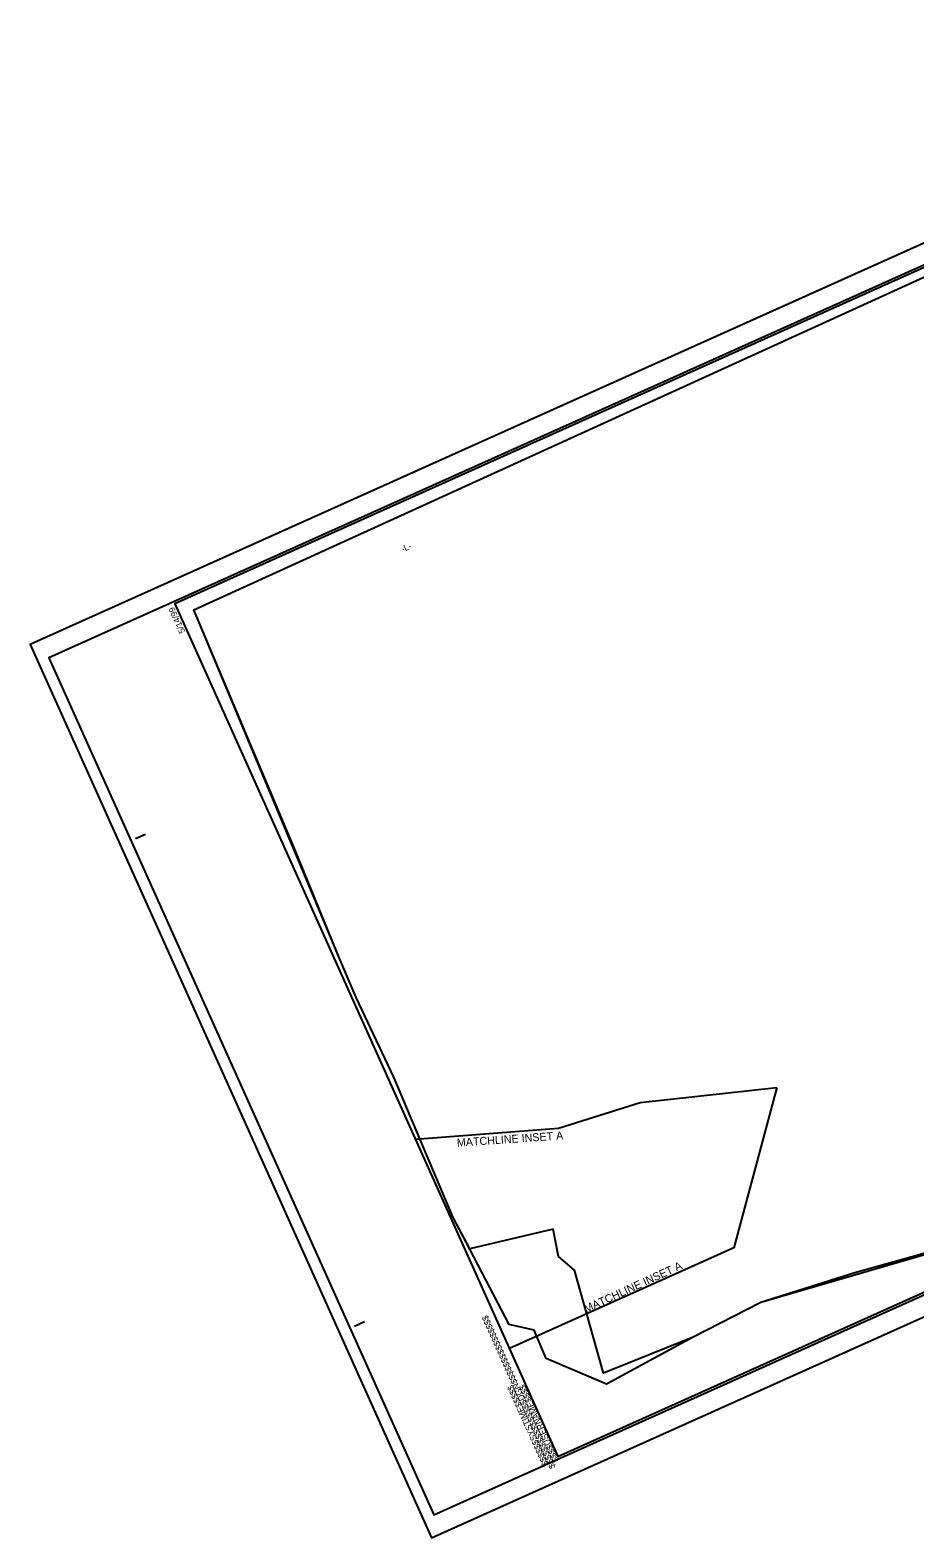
# Model space of a CAD drawing. Extents: x 553939 to 555925, y 502653 to 504347.
# Drawn here: x 553939 to 554932, y 502653 to 504347 of the extents above; entities that cross this region are included whole.
import ezdxf

# ---------------------------------------------------------------- set-up
doc = ezdxf.new("R2010")
doc.units = 0
for name, color, linetype in [('Matchline', 7, 'Continuous'), ('Matchline Text', 7, 'Continuous'), ('Prop Horizontal Alignment Station Label', 7, 'Continuous'), ('Sheet Border Standard 30in CELL', 7, 'Continuous'), ('Sheet Clip Boundary CELL', 7, 'Continuous'), ('Sheet Cutting Line CELL', 7, 'Continuous'), ('Sheet Plot Border Inside CELL', 7, 'Continuous'), ('Sheet Plot Border Outside CELL', 7, 'Continuous')]:
    doc.layers.add(name, color=color, linetype=linetype)

msp = doc.modelspace()

# ---------------------------------------------------------------- linework, layer by layer
at = {"layer": 'Matchline'}
for p, q in [((554623.6, 503142.1), (554777.2, 503159.2)), ((554777.2, 503159.2), (554728.8, 502978.9)), ((554532, 503113.5), (554623.6, 503142.1)), ((554371.3, 503101), (554532, 503113.5)), ((554728.8, 502978.9), (554476.9, 502865.8))]:
    msp.add_line(p, q, dxfattribs=at)
at = {"layer": 'Sheet Border Standard 30in CELL'}
for p, q in [((554102.1, 503702.8), (554102.1, 503702.8)), ((554056.9, 503438.6), (554068.3, 503443.7)), ((554302.7, 502891.2), (554314.1, 502896.4))]:
    msp.add_line(p, q, dxfattribs=at)
msp.add_lwpolyline([(555469.6, 504316.8), (554101.2, 503702.4), (554531.3, 502744.5), (555899.7, 503359)], close=True, dxfattribs=at)
at = {"layer": 'Sheet Clip Boundary CELL'}
for points in [[(555094.7, 503015.3), (554759.3, 502917.8), (554683, 502878.6), (554586, 502826.1), (554517.9, 502854.7), (554504.5, 502886.7), (554476.7, 502893.1), (554428.4, 502985.5), (554413.3, 503013.9), (554346.9, 503170.6), (554304.9, 503260.3), (554285.2, 503305.8), (554122.4, 503695.7), (555128.4, 504154.2)], [(555094.7, 503015.3), (554864.6, 502951), (554759.3, 502917.8), (554683, 502878.6), (554582.3, 502838.3), (554549.8, 502954), (554532.1, 502969.2), (554526, 503000), (554432.2, 502977.8), (554413.3, 503013.9), (554346.9, 503170.6), (554304.9, 503260.3), (554285.2, 503305.8), (554236.8, 503423.9), (554122.4, 503695.7), (555128.4, 504154.2)]]:
    msp.add_lwpolyline(points, dxfattribs=at)
at = {"layer": 'Sheet Cutting Line CELL'}
for p, q in [((555474.9, 504346.6), (553938.6, 503656.8)), ((553938.6, 503656.8), (554389.2, 502653.3)), ((554389.2, 502653.3), (555925.5, 503343.1))]:
    msp.add_line(p, q, dxfattribs=at)
at = {"layer": 'Sheet Plot Border Inside CELL'}
msp.add_lwpolyline([(555480, 504324.3), (553959.7, 503641.6), (554391.9, 502679.1), (555912.2, 503361.8)], close=True, dxfattribs=at)
at = {"layer": 'Sheet Plot Border Outside CELL'}
msp.add_lwpolyline([(555474.9, 504346.6), (553938.6, 503656.8), (554389.2, 502653.3), (555925.5, 503343.1)], close=True, dxfattribs=at)

# ---------------------------------------------------------------- texts
at = {"layer": 'Matchline Text'}
for rotation, p in [(3.9694, (554418.1, 503092.6)), (24.7503, (554563.1, 502905.8))]:
    msp.add_text('MATCHLINE INSET A', height=9, rotation=rotation, dxfattribs=at).set_placement(p)
at = {"layer": 'Prop Horizontal Alignment Station Label'}
msp.add_text('-L-', height=7, rotation=24.1816, dxfattribs=at).set_placement((554357.1, 503760.1))
at = {"layer": 'Sheet Border Standard 30in CELL'}
for s, p in [('5/14/99', (554112.9, 503671)), ('$$$$$$$$$$$$$$$$DGN$$$$$$$$$$$$$$$$', (554528.7, 502732.9)), ('$$$$$$SYSTIME$$$$$', (554520.8, 502735.7)), ('$$$$USERNAME$$$$', (554532.5, 502739.9))]:
    msp.add_text(s, height=7, rotation=114.1816, dxfattribs=at).set_placement(p)

doc.saveas('drawing.dxf')
